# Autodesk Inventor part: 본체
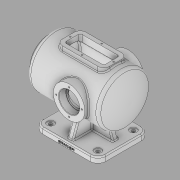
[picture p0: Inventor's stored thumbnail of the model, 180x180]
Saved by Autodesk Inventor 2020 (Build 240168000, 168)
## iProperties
Created: 2021-11
Part Number: 본체
Material: 일반
Document SubType Name: Modeling
Designer: Administrator
Density: 1 g/cm^3
Appearance: 기본값
Author: Administrator
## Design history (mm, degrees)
sketch "스케치1"
  geometry: L1 (80, -65)-(-80, -65); L2 (-80, -65)-(-80, 65); L3 (-80, 65)-(80, 65); L4 (80, 65)-(80, -65); L5 (80, -65)-(-80, 65); L6 (-80, -65)-(80, 65); 1 further point
  constraints: 12 end point, 2 midpoint, 2 parallel, 1 horizontal, 1 perpendicular
  dimensions: "d0" = 160 distance of L2.end L3.end; "d1" = 130 distance of L1.end L2.end
extrude "돌출1" new body sketch "스케치1" distance "d2" = 14; taper "d3" = 0 deg
sketch "스케치2"
  geometry: L1 (110.117, -100)-(110.117, -147.5); L2 (110.117, -147.5)-(100.117, -147.5); L3 (100.117, -147.5)-(100.117, -165); L4 (100.117, -165)-(-79.883, -165); L5 (-99.883, -100)-(110.117, -100); L6 (80, 14)-(-80, 14) reference; A1 r 100 centre (0, -104.844) between (-99.883, -100) and (-79.883, -165); 1 further point
  constraints: 10 end point, 3 perpendicular, 2 point on circle, 1 centre point, 1 horizontal, 1 vertical, 1 vertical alignment
  dimensions: "d4" = 114 distance from line of L1.start L6; "d5" = 95 diameter of L2 L5; "d6" = 10 distance of L1.end L2.end; "d7" = 210 distance of L5.start L1.start; "d8" = 100 radius of A1; "d9" = 130 diameter of L4 L5; "d11" = 180 distance of L3.end L4.end
revolve "회전1" sketch "스케치2" stored, may be unused: angle "d12" = 90 deg
sketch "스케치3"
  geometry: L1 (110.117, -52.5)-(110.117, -147.5) reference; L2 (100.117, -165)-(-79.883, -165) reference; L3 (110.117, -132.5)-(85.117, -132.5); L4 (85.117, -132.5)-(85.117, -155); L5 (85.117, -155)-(-74.729, -155); L6 (110.117, -100)-(-99.884, -100); L7 (110.117, -132.5)-(110.117, -100); A1 r 100 centre (0, -104.844) between (-100, -104.844) and (-79.883, -165) reference; A2 r 100 centre (0, -104.844) between (-99.883, -100) and (-100, -104.844) reference; A3 r 90 centre (0, -104.844) between (-89.87, -100) and (-74.729, -155); 2 further points
  constraints: 10 end point, 3 point on line, 2 horizontal, 2 perpendicular, 2 point on circle, 1 centre point, 1 collinear, 1 midpoint
  dimensions: "d14" = 25 distance of L3.start L3.end; "d15" = 65 diameter of L3 L6; "d16" = 110 diameter of L5 L6; "d103" = 10 radial gap between concentric circles of A1 A3
revolve "회전2" sketch "스케치3" stored, may be unused: angle "d17" = 90 deg
node "작업 평면1"
sketch "스케치7"
  geometry: L1 (-60.117, 30)-(59.883, 30); L2 (59.883, 30)-(59.883, -30); L3 (59.883, -30)-(-60.117, -30); L4 (-60.117, -30)-(-60.117, 30); L5 (-60.117, 30)-(59.883, -30); L6 (59.883, 30)-(-60.117, -30); L7 (-110.117, -47.5)-(-110.117, 47.5) reference; 3 further points
  constraints: 12 end point, 3 midpoint, 2 parallel, 1 horizontal, 1 horizontal alignment, 1 perpendicular
  dimensions: "d38" = 120 distance of L2.end L3.end; "d39" = 50 distance between parallel lines of L4 L7; "d40" = 60 distance of L1.end L2.end
extrude "돌출2" join sketch "스케치7" stored distance "d41" = 14; taper "d42" = 0 deg
sketch "스케치8"
  geometry: L1 (-59.883, -30)-(-59.883, 30) reference; L2 (60.117, -30)-(-59.883, -30) reference; L3 (60.117, 30)-(60.117, -30) reference; L4 (-59.883, 30)-(60.117, 30) reference; L5 (-49.883, -20)-(-49.883, 20); L6 (-49.883, 20)-(50.117, 20); L7 (50.117, 20)-(50.117, -20); L8 (50.117, -20)-(-49.883, -20); 1 further point
  constraints: 8 end point, 3 other
  dimensions: "d43" = 10 distance between parallel lines of L2 L8
extrude "돌출3" cut sketch "스케치8" stored distance "d44" = 14; taper "d45" = 0 deg
sketch "스케치9"
  geometry: L1 (-49.883, 20)-(50.117, 20) reference; L2 (50.117, 20)-(50.117, -20) reference; L3 (50.117, -20)-(-49.883, -20) reference; L4 (-49.883, -20)-(-49.883, 20) reference; L5 (-59.883, -30)-(-59.883, 30) reference; L6 (60.117, -30)-(-59.883, -30) reference; L7 (60.117, 30)-(60.117, -30) reference; L8 (-59.883, 30)-(60.117, 30) reference; L9 (-54.883, -25)-(55.117, -25); L10 (55.117, -25)-(55.117, 25); L11 (55.117, 25)-(-54.883, 25); L12 (-54.883, 25)-(-54.883, -25); L13 (60.117, 0)-(-59.883, 0); L14 (0.117, -30)-(0.117, 30); 5 further points
  constraints: 12 end point, 8 midpoint, 4 point on line, 3 other
  dimensions: "d46" = 5 distance between parallel lines of L3 L9
hole "구멍2" sketch "스케치9" at (0.117, -25), (55.117, 0), (0.117, 25), (-54.883, 0) diameter "d47" = 3.45873; stored, may be unused: countersink angle "d51" = 90 deg, drill point angle "d53" = 118 deg; dims "d48" = 9, "d49" = 8, "d50" = 4, "d52" = 11
node "작업 평면2"
sketch "스케치10"
  geometry: L1 (100.117, -35)-(100.117, -165) reference; C1 r 40 at (-16.883, -100); 2 further points
  constraints: 1 centre point, 1 horizontal alignment, 1 midpoint
  dimensions: "d55" = 40 radius of C1; "d102" = 117 distance from line of C1.centre L1
extrude "돌출4" join sketch "스케치10" stored distance "d56" = 14; taper "d57" = 0 deg
sketch "스케치11"
  geometry: C1 r 40 at (0, 0) reference; 2 further points
  constraints: 1 coincident
hole "구멍3" sketch "스케치11" at (0, 0) diameter "d58" = 42; stored, may be unused: countersink angle "d62" = 90 deg, drill point angle "d64" = 0 deg; dims "d59" = 11, "d60" = 52, "d61" = 18, "d63" = 13
chamfer "모따기1" distance "d65" = 1; stored, may be unused: second distance "d66" = 2, angle "d67" = 45 deg
chamfer "모따기2" distance "d68" = 0.3; stored, may be unused: second distance "d69" = 2, angle "d70" = 45 deg
sketch "스케치12"
  geometry: L1 (-80, 0)-(80, 0) reference; L2 (60, 0)-(0, 0); L3 (100.117, -35)-(-79.883, -35) reference; L4 (60, 0)-(47.261, -35); L5 (47.261, -35)-(-47.261, -35); L6 (-47.261, -35)-(-60, 0); L7 (-60, 0)-(0, 0)
  constraints: 10 end point, 4 point on line, 2 collinear
  dimensions: "d71" = 20 distance of L1.end L2.start; "d72" = 110 deg angle of L4 L1; "d73" = 110 deg angle of L1 L6; "d74" = 20 distance of L1.start L6.end
extrude "돌출5" join sketch "스케치12" stored distance "d75" = 14; taper "d76" = 0 deg
sketch "스케치13"
  geometry: L1 (-65, 0)-(65, 0) reference; L2 (55, 0)-(43.67, -31.13); 1 further point
  constraints: 2 end point, 1 point on line
  dimensions: "d77" = 10 distance of L1.end L2.start; "d78" = 110 deg angle of L2 L1
feature "리브2" sketch "스케치13" dims "d79" = 1, "d80" = 14, "d81" = 0, "d82" = 0, "d83" = 1, "d84" = 1
fillet "모깎기1" dims "d85" = 3
fillet "모깎기2" dims "d86" = 20
sketch "스케치14"
  geometry: A1 r 20 centre (60, 45) between (80, 45) and (60, 65) reference; A2 r 20 centre (60, -45) between (60, -65) and (80, -45) reference; A3 r 20 centre (-60, -45) between (-80, -45) and (-60, -65) reference; A4 r 20 centre (-60, 45) between (-60, 65) and (-80, 45) reference; 5 further points
  constraints: 4 coincident
hole "구멍4" sketch "스케치14" at (60, 45), (60, -45), (-60, -45), (-60, 45) diameter "d87" = 9; stored, may be unused: countersink angle "d91" = 90 deg, drill point angle "d93" = 0 deg; dims "d88" = 11, "d89" = 18, "d90" = 2, "d92" = 13
fillet "모깎기3" dims "d94" = 3
fillet "모깎기4" dims "d95" = 10
fillet "모깎기5" dims "d96" = 15, "d97" = 5
fillet "모깎기6" dims "d98" = 3
sketch "스케치15"
  geometry: L1 (10.46, 10.763)-(109.54, 10.763); L2 (109.54, 10.763)-(109.54, -0.763); L3 (109.54, -0.763)-(10.46, -0.763); L4 (10.46, -0.763)-(10.46, 10.763); L5 (10.46, 10.763)-(109.54, -0.763); L6 (120, 0)-(0, 0) reference; 2 further points
  constraints: 2 end point, 1 midpoint, 1 vertical alignment, 2 other
  dimensions: "d99" = 5 distance from line of L6 point (60, 5)
feature "엠보싱1" sketch "스케치15" dims "d100" = 0.5, "d101" = 0
fillet "모깎기7" dims "d104" = 3
sketch "스케치16" dims "d106" = 65
  geometry: L1 (0, 0)-(0, 32.5); C1 r 27 at (0, 0) reference; 2 further points
  constraints: 2 coincident, 2 end point, 1 vertical, 1 vertical alignment, 2 other
hole "구멍5" sketch "스케치16" at (0, 32.5) diameter "d107" = 3.45873; stored, may be unused: countersink angle "d111" = 90 deg, drill point angle "d113" = 118 deg; dims "d108" = 11, "d109" = 18, "d110" = 2, "d112" = 13
sketch "스케치17" dims "d117" = 40
  geometry: L1 (0, 0)-(-40, 0); C1 r 32.5 at (0, 0) reference; 2 further points
  constraints: 2 coincident, 2 end point, 1 horizontal, 1 horizontal alignment, 2 other
hole "구멍6" sketch "스케치17" at (-40, 0) diameter "d118" = 3.45873; stored, may be unused: countersink angle "d122" = 90 deg, drill point angle "d124" = 118 deg; dims "d119" = 11, "d120" = 18, "d121" = 2, "d123" = 13
node "솔리드1"
mirror "미러1"
mirror "미러2"
pattern_circular "원형 패턴2" dims angle "d115" = 360 deg
mirror "미러3"
pattern_circular "원형 패턴3" dims angle "d126" = 360 deg
node "투영된 루프2"
node "투영된 루프3"
feature "A9D066F2-1C7D-4E18-AEED-F7BC21143FA4" dims "d87" = 9, "d88" = 11, "d89" = 18, "d90" = 2, "d91" = 90 deg, "d92" = 13, "d93" = 0
other parameters: "d54" = 75
